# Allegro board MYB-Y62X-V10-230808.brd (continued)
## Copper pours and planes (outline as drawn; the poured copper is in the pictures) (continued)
GND on TOP: 170.1,77.6 169.72,77.6 168.45,76.33 163.75,76.33 162.23,77.85 162.23,81.53 161.72,82.04 160.07,82.04 159.94,81.92 159.94,80.39 159.56,80.01 156.38,80.01 155.62,80.77 153.84,80.77 151.68,82.93 135.56,82.93 134.79,82.17 134.79,79.88 135.68,78.99 138.22,78.99 141.91,75.31 151.56,75.31 151.94,75.69 159.99,75.69 160.63,75.06 161.24,75.06 163.24,73.05 163.24,71.12 162.1,69.98 160.83,69.98 160.75,69.9 160.75,69.32 160.85,69.22 161.59,69.22 161.9,68.91 161.9,67.92 161.54,67.56 151.05,67.56 148.26,64.77 148.26,61.47 148.89,60.83 153.72,60.83 157.4,64.52 171.88,64.52 172.13,64.77 172.13,80.14 171.88,80.39 169.72,80.39 169.46,80.64 169.08,80.64 168.96,80.52 168.96,79.25 169.85,78.36 169.85,77.85 169.72,77.72 170.1,77.72
GND on TOP: 168.96,84.07 171.75,84.07 172,83.82 172,82.3 171.75,82.04 168.96,82.04 168.7,82.3 168.7,83.82
GND on TOP: 144.95,56.01 144.95,55.5 146.48,53.98 149.4,53.98 149.53,53.85 149.53,52.32 149.78,52.07 152.83,52.07 153.21,52.45 153.21,54.99 153.46,55.24 154.99,55.24 155.24,54.99 155.24,52.58 154.43,51.77 154.43,49.73 154.28,49.58 153.39,49.58 153.39,50.75 152.7,51.44 149.27,51.44 149.02,51.69 149.02,53.21 148.76,53.47 146.48,53.47 145.84,54.1 145.21,54.1 144.95,53.85 144.95,53.47 144.83,53.34 144.06,53.34 143.94,53.47 143.94,56.01 144.06,56.13 144.83,56.13
GND on TOP: 147.62,90.68 147.37,90.93 147.37,94.39 148.38,95.4 148.38,96.9 148.51,97.03 149.78,97.03 149.91,96.9 149.91,92.74 150.57,92.08 154.22,92.08 154.35,91.95 154.35,90.93 154.1,90.68
GND on BOTTOM: 108,100.33 109.9,98.42 113.33,98.42 113.84,97.92 113.84,96.39 113.58,96.14 104.95,96.14 103.42,97.66 103.42,100.08 103.68,100.33
GND on BOTTOM: 30.11,124.49 104.06,124.49 104.06,108.71 103.17,107.82 99.74,107.82 99.23,108.33 99.23,111.76 97.96,113.03 92.63,113.03 89.07,116.59 33.96,116.59 32.11,114.74 30.91,114.74 30.11,115.54
GND on BOTTOM: 162.99,42.55 162.99,41.15 162.48,40.64 161.46,40.64 160.96,41.15 160.96,42.29 161.34,42.67 162.86,42.67
GND on BOTTOM: 18.72,83.06 18.72,81.28 18.84,81.15 20.11,81.15 20.37,81.41 20.37,83.06 20.11,83.31 18.97,83.31
GND on BOTTOM: 30.15,56.39 43.61,56.39 46.15,53.85 46.15,52.07 45.51,51.44 33.63,51.44 33.63,53.52 33.38,53.76 30.36,53.76 30.02,54.1 30.02,56.26
GND on BOTTOM: 88.44,34.9 92.1,34.9 92.22,34.77 92.22,32.92 91.41,32.11 88.41,32.11 88.21,32.31 88.21,34.67
GND on BOTTOM: 86.48,33.88 86.51,33.86 86.51,32.92 88.18,31.24 92.05,31.24 92.48,30.81 92.48,30.07 92.2,29.79 87.63,29.79 87.45,29.97 87.45,30.33 87.5,30.38 87.5,31.06 87.14,31.42 85.67,31.42 85.26,31.83 85.26,36.07 84.37,36.96 84.37,38.73 84.07,39.04 81.73,39.04 81.68,39.09 81.68,39.52 83.26,39.52 83.51,39.78 83.51,40.13 83.59,40.21 83.94,40.21 85.04,39.12 86.36,39.12 86.48,38.99
GND on BOTTOM: 111.76,34.87 115.41,34.87 115.57,34.72 115.57,32.89 114.96,32.28 111.68,32.28 111.48,32.49 111.48,34.59
GND on BOTTOM: 166.92,39.5 166.67,39.75 166.67,41.66 167.69,42.67 167.81,42.67 168.07,42.93 168.07,46.99 167.56,47.5 167.56,56.13 165.02,58.67 157.4,58.67 156.26,57.53 156.26,54.48 156,54.23 154.35,54.23 154.1,54.48 154.1,56.39 153.23,57.25 148.87,57.25 145.67,60.45 145.67,72.72 146.05,73.1 147.67,73.1 148.87,71.91 148.87,71.15 148.69,70.97 146.71,70.97 146.48,70.74 146.48,68.48 147.11,67.84 150.01,67.84 150.34,67.51 150.34,64.57 150.97,63.93 170.25,63.93 170.91,64.59 172.18,64.59 172.59,64.19 172.59,41.58 172.16,41.15 170.1,41.15 169.97,41.02 169.97,39.75 169.72,39.5
GND on BOTTOM: 72.06,39.47 71.47,40.06 71.47,44.86 73.61,46.99 73.61,47.98 73.88,48.26 77.59,48.26 78.94,46.91 86.61,46.91 87.02,46.51 87.02,42.9 85.82,41.71 83.21,41.71 82.6,41.1 80.26,41.1 78.63,39.47
GND on BOTTOM: outline of 93 points within 40.56,7.24 123.77,41.91
GND on BOTTOM: 132,33.48 125.09,33.48 124.81,33.2 124.81,28.02 125.29,27.53 127.33,27.53 127.71,27.15 127.71,25.91 127.96,25.65 128.37,25.65 128.85,26.14 130.35,26.14 130.73,25.76 131.54,25.76 132.05,26.26 133.14,26.26 133.4,26.52 134.57,26.52 134.69,26.64 134.69,31.22 134.57,31.34 133.42,31.34 132.1,32.66 132.1,33.38
GND on BOTTOM: 115.35,95.08 115.01,94.74 115.01,91.08 115.46,90.63 115.85,90.63 116.53,89.94 119.88,89.94 120.19,89.64 144.04,89.64 144.55,89.13 145.84,89.13 146.2,89.48 152.29,89.48 153.72,90.91 153.72,92.94 150.9,95.76 131.42,95.76 130.74,95.08
GND on BOTTOM: 14.78,6.22 14.52,6.48 14.52,11.05 15.16,11.68 16.43,11.68 17.45,12.7 17.45,14.35 16.18,15.62 14.52,15.62 12.87,13.97 8.56,13.97 7.92,14.61 7.92,86.06 8.3,86.44 12.92,86.44 13,86.36 13,62.74 14.91,60.83 25.57,60.83 26.21,60.2 26.21,57.78 25.07,56.64 25.07,52.07 24.68,51.69 18.97,51.69 18.72,51.94 18.72,52.81 19.35,53.44 19.35,55.5 18.97,55.88 14.02,55.88 13.13,54.99 13.13,34.16 13.64,33.66 19.15,33.66 20.29,34.8 25.83,34.8 33.45,27.18 36.11,27.18 36.29,27 36.29,25.83 35.99,25.53 35.48,25.53 32.18,22.23 32.18,17.02 29.64,17.02 29.13,16.51 29.13,12.95 28.49,12.32 20.37,12.32 18.84,10.79 18.84,7.37 17.7,6.22
GND on BOTTOM: 65.02,112.93 79.24,112.93 79.7,113.39 87.47,113.39 88.46,112.39 88.46,109.63 87.68,108.84 87.68,107.29 87.58,107.19 85.67,109.09 82.72,109.09 82.17,109.65 81.05,109.65 80.92,109.78 80.92,110.54 80.82,110.64 74.06,110.64 73.45,110.03 68.09,110.03 68.02,109.96 68.02,106.48 67.59,106.05 65.58,106.05 65.17,105.64 65.17,103.38 64.92,103.12 63.34,103.12 63.19,102.97 62.51,102.97 60.3,105.18 45.11,105.18 44.65,105.64 44.65,110.11 45.08,110.54 64.74,110.54 64.92,110.72 64.92,112.83
GND on BOTTOM: 158.43,8.52 159.18,9.27 170.73,9.27 170.86,9.4 170.86,13.46 172,14.61 172,35.69 171.12,36.58 165.15,36.58 164.38,35.81 164.38,21.34 163.11,20.07 160.57,20.07 156.51,16 151.3,16 151.24,16.07 150.22,16.07 149.78,15.62 149.78,13.46 148.23,11.91 148.23,8.56 148.92,7.87 158.37,7.87 158.43,7.94
GND on BOTTOM: 115.58,31.22 115.58,29.97 115.45,29.84 110.88,29.84 110.75,29.97 110.75,31.24 110.5,31.5 108.85,31.5 108.47,31.88 108.47,34.38 108.71,34.62 109.29,34.62 110.03,33.88 110.03,32.94 111.76,31.22
GND on BOTTOM: 56.93,47.51 56.93,49.16 58.97,51.21 58.97,60.2 55.93,63.25 55.93,72.26 56.31,72.64 61.34,72.64 63.92,70.07 63.92,50.95 62.66,49.7 62.66,49.66 62.53,49.53 62.53,47.37 62.4,47.24 57.2,47.24
GND on BOTTOM: 19.5,107.49 18.67,108.33 18.67,111.33 17.8,112.19 14.78,112.19 13.76,113.21 13.76,117.35 14.14,117.73 16.18,117.73 17.19,118.75 17.19,120.65 16.18,121.67 14.4,121.67 14.04,122.02 14.04,124.49 29.38,124.49 29.38,112.14 24.74,107.49
GND on BOTTOM: 142.82,16.51 142.82,14.88 143.02,14.68 145.59,14.68 146.38,13.89 146.38,13.11 146.6,12.88 148.26,12.88 148.76,13.39 148.76,13.92 148.56,14.12 147.27,14.12 146.63,14.76 146.63,16.79 146.35,17.07 143.18,17.07 142.97,17.27 142.97,17.68 143.18,17.88 143.84,17.88 143.89,17.93 143.89,18.47 143.66,18.69 140.64,18.69 140.1,19.23 136.78,19.23 136.39,18.85 136.39,11.35 136.62,11.13 137.79,11.13 137.94,11.28 137.94,16.71 138.96,17.73 141.6,17.73
GND on BOTTOM: 39.42,112.65 37.13,112.65 25.45,100.97 19.22,100.97 18.08,99.82 16.56,99.82 16.18,99.44 16.18,97.54 17.83,95.89 28.88,95.89 33.05,91.71 53.91,91.71 54.53,92.33 55.95,92.33 56.43,91.85 56.43,88.14 57.32,87.25 63.24,87.25 64,88.01 64,94.46 63.6,94.87 61.77,94.87 57.83,98.81 41.96,98.81 40.18,100.58 40.18,111.89
GND on BOTTOM: 38.48,82.98 38.1,82.6 38.1,79.3 37.66,78.87 36.22,78.87 35.86,79.22 35.86,80.37 35.66,80.57 29.21,80.57 28.16,79.53 28.16,74.22 28.9,73.48 45.41,73.48 46.43,74.5 46.43,82.14 49.75,85.47 56.03,85.47 56.28,85.72 56.28,86.11 53.89,88.49 49.73,88.49 49.4,88.82 30.02,88.82 29.92,88.72 29.92,87.93 31.62,86.23 31.62,84.99 31.97,84.63 38.32,84.63 38.48,84.48
GND on BOTTOM: 155.37,84.96 154.73,84.96 153.46,83.69 140.48,83.69 140.18,83.39 140.18,82.78 144.6,78.36 159.81,78.36 160.07,78.11 160.96,78.11 164.13,81.28 164.13,86.11 162.48,87.76 161.46,87.76 161.08,87.38 161.08,86.49 163.24,84.33 163.24,82.3 162.99,82.04 162.35,82.04 161.21,83.19 161.21,84.2 160.32,85.09 155.49,85.09
GND on BOTTOM: 137.08,79.45 135.07,79.45 134.72,79.1 134.72,78.71 134.51,78.51 131.95,78.51 131.06,77.62 131.06,75.06 136.01,70.1 136.01,69.32 142.41,62.92 142.41,54.74 143.48,53.67 144.88,53.67 147.47,51.08 150.8,51.08 151.02,51.31 151.02,52.37 151.01,52.39 151.01,52.74 144.27,59.49 144.27,72.26
GND on BOTTOM: 162.61,97.16 166.04,97.16 166.42,97.54 166.42,99.44 166.16,99.69 161.97,99.69 161.72,99.44 161.72,98.04
GND on BOTTOM: 124.13,32.16 122.45,32.16 122.12,31.83 122.12,30.76 121.81,30.45 120.98,30.45 120.54,30.02 120.54,24.31 120.93,23.93 126.59,23.93 126.72,24.05 126.72,26.34 126.39,26.67 124.66,26.67 124.3,27.03 124.3,31.98
GND on BOTTOM: 80.56,24.23 79.88,24.92 79.88,24.94 73.71,31.11 73.71,35.31 73.96,35.56 76.12,35.56 76.5,35.94 76.5,36.58 76.75,36.83 79.8,36.83 79.93,36.7 79.93,35.05 80.56,34.42 81.45,34.42 83.1,32.77 83.1,25.04 83.21,24.94 84.63,24.94 85.19,25.5 95.58,25.5 95.93,25.86 95.93,26.39 96.01,26.47 97.43,26.47 97.99,27.03 97.99,28.68 98.29,28.98 99.51,28.98 101.27,30.73 101.27,44.07 99.61,45.72 99.61,46.61 100.12,47.12 103.04,47.12 103.42,46.74 103.42,42.16 104.57,41.02 104.57,40.26 103.93,39.62 103.93,37.26 104.11,37.08 105.2,37.08 105.71,36.58 105.71,24.56 105.38,24.23
GND on BOTTOM: 162.96,22.91 162.25,23.62 157.12,23.62 156.74,24 156.74,31.7 155.8,32.64 153.72,32.64 153.21,32.13 153.21,28.32 153.46,28.07 154.86,28.07 154.99,27.94 154.99,26.42 154.73,26.16 153.84,26.16 153.46,26.54 146.35,26.54 145.21,27.69 145.21,32 145.46,32.26 146.48,32.26 147.62,33.4 147.62,34.67 159.94,34.67 161.82,32.79 161.82,30.76 162.02,30.56 162.35,30.56 162.63,30.84 163.34,30.84 163.52,30.66 163.52,23.14 163.29,22.91
GND on BOTTOM: 52.65,61.39 54.61,61.39 56.94,59.05 56.94,53.16 51.33,47.55 49.93,47.55 49.35,48.13 49.35,53.14 48.31,54.18 48.31,58.98 48.99,59.66 50.92,59.66
GND on BOTTOM: 29.78,39.51 30.78,40.51 42.67,40.51 43.28,39.9 43.28,34.04 42.34,33.1 35.94,33.1 34.91,32.07 31.15,32.07 29.78,33.44
GND on ART03: 19.53,107.49 18.69,108.33 18.69,111.28 17.78,112.19 14.8,112.19 14.04,112.95 14.04,124.49 29.36,124.49 29.36,109.98 26.87,107.49
GND on ART03: 166.92,40.26 168.83,40.26 169.21,39.88 169.21,24.38 164.13,19.3 160.96,19.3 160.96,21.59 164,24.64 164,37.34
GND on ART03: 72.82,35.05 72.82,33.02 73.33,32.51 82.85,32.51 85.39,29.97 87.04,29.97 87.42,30.35 87.42,30.61 85.64,32.38 84.5,32.38 82.85,34.04 81.2,34.04 81.07,33.91 78.79,33.91 77.52,35.18 72.94,35.18
GND on ART03: 68.09,124.49 103.93,124.49 103.93,108.76 102.56,107.39 100.02,107.39 98.4,109.02 98.4,116.28 98.42,116.31 98.01,116.71 97.2,116.71 96.19,115.7 67.92,115.7 67.76,115.85 67.76,124.16
GND on ART03: 33.61,99.31 42.21,99.31 42.87,98.65 42.87,83.85 42.13,83.11 30.7,83.11 30.37,83.44 28.93,83.44 28.62,83.13 28.62,81.46 28.47,81.31 26.54,81.31 26.25,81.6 26.25,91.95
GND on ART03: 77.64,7.24 76.5,8.38 76.5,19.05 75.99,19.56 73.2,19.56 72.94,19.3 72.94,14.73 73.33,14.35 73.33,13.21 73.07,12.95 72.06,12.95 71.8,12.7 71.8,10.41 71.42,10.03 68.88,10.03 67.74,8.89 62.28,8.89 61.64,9.53 61.64,18.92 61.9,19.18 63.55,19.18 64.69,20.32 64.69,23.75 64.94,24 67.23,24 69.8,21.44 69.82,21.46 76.63,21.46 77.39,22.23 119.81,22.23 123.36,18.67 123.36,17.91 123.11,17.65 120.44,17.65 117.39,20.7 106.22,20.7 105.33,19.81 105.33,16.26 105.08,16 98.22,16 97.58,16.64 97.58,18.8 95.8,20.57 83.36,20.57 82.72,19.94 82.72,16.26 82.47,16 80.95,16 79.93,14.99 79.93,9.53 80.44,9.02 80.44,7.37 80.31,7.24
GND on ART03: 139.24,70.1 140.64,68.71 150.44,68.71 151,69.27 151.61,69.27 151.84,69.49 151.84,70.26 154.22,72.64 154.22,76.38 153.77,76.83 140.03,76.83 139.24,76.05
GND on ART03: 157.53,53.19 157.53,52.45 156.89,51.82 156.89,50.8 156.38,50.29 154.22,50.29 153.93,50 153.95,49.99 153.95,49.73 154.05,49.63 157.48,49.63 161.26,45.85 162.78,45.85 163.06,46.13 163.06,48.26 163.24,48.44 163.88,48.44 164,48.31 164.23,48.31 164.38,48.46 164.38,49.53 164.26,49.66 163.42,49.66 162.98,50.1 162.98,51.02 159.36,54.64 157.73,54.64 157.54,54.44 157.54,53.2
GND on ART03: 114.73,94.87 130.6,94.87 131.75,96.01 156.51,96.01 159.3,93.22 170.48,93.22 171.88,91.82 171.88,72.06 171.22,71.4 168.65,71.4 162.07,77.98 157.65,77.98 157.63,78 130.09,78 129.43,78.66 129.43,87.3 131.34,89.2 131.34,90.42 131.47,90.55 129.59,90.55 128.06,92.08 126.67,92.08 126.41,92.33 119.81,92.33 118.79,91.31 115.62,91.31 114.73,92.2
GND on ART03: 23.67,90.7 22.58,90.7 22.32,90.45 22.32,88.29 18.82,84.79 18.82,80.62 19.02,80.42 22.96,80.42 23.8,81.25 23.8,90.58
GND on ART03: 28.88,81.03 28.88,78.56 29.08,78.36 40.03,78.36 40.18,78.51 40.18,81.66 40.05,81.79 37,81.79 36.5,81.28 29.13,81.28
GND on ART03: 50.34,42.8 50.34,35.46 51.2,34.59 52.7,34.59 53.01,34.29 55.95,34.29 56.68,35.01 60.97,35.01 62.53,36.58 62.53,41.53 61.26,42.8
GND on ART03: 112.44,44.45 120.82,44.45 126.03,49.66 126.03,49.68 131.43,55.08 131.43,55.89 131.31,56.01 130.76,56.01 129.33,54.58 116.12,54.58 115.57,54.03 115.57,52.45 114.7,51.59 111.63,51.59 110.28,50.24 110.28,46.61
GND on ART03: 153.46,25.53 152.19,26.8 147.37,26.8 145.72,28.45 145.72,41.05 147.09,42.42 162.73,42.42 162.99,42.16 162.99,40.51 162.73,40.26 160.19,40.26 159.91,40.54 155.09,40.54 154.86,40.31 154.86,37.95 154.43,37.52 151.35,37.52 151.05,37.21 151.05,35.64 151.38,35.31 154.91,35.31 155.49,34.72 155.49,26.16 154.86,25.53
GND on ART03: 10.59,89.36 11.98,90.75 11.98,102.36 13.51,103.89 15.16,103.89 18.21,106.93 18.21,111 17.45,111.76 14.27,111.76 13.51,112.52 13.51,114.55 13.38,114.68 8.05,114.68 7.79,114.43 7.79,89.66 8.1,89.36
GND on ART03: 60.75,95.89 63.29,95.89 64.05,95.12 64.05,89.15 63.8,88.9 63.8,86.49 62.91,85.6 62.91,83.69 63.17,83.44 64.44,83.44 64.82,83.06 64.82,51.38 64.33,50.9 61.18,50.9 60.7,51.38 60.7,52.6 61.11,53.01 62.23,53.01 62.73,53.52 62.73,66.65 61.34,68.05 58.49,68.05 57.7,68.83 57.7,88.52 57.2,89.03 57.2,92.33
GND on ART03: 85.26,34.16 85.26,33.66 88.06,30.86 95.68,30.86 97.71,32.89 109.52,32.89 109.77,33.15 109.77,34.42 109.52,34.67 98.85,34.67 98.6,34.92 96.06,34.92 95.55,34.42 85.52,34.42
GND on ART03: 65.58,36.07 73.2,36.07 75.48,38.35 80.56,38.35 82.22,36.7 89.45,36.7 89.96,36.2 95.42,36.2 96.19,36.96 96.19,37.85 95.55,38.48 82.6,38.48 81.2,39.88 75.99,39.88 75.23,40.64 66.7,40.64 66.62,40.72 66.62,41.1 67.13,41.61 71.62,41.61 71.93,41.91 71.93,43 72.39,43.46 72.39,44.25 72.01,44.63 65.1,44.63 64.36,43.89 64.36,37.29
GND on ART03: 40.56,108.69 39.59,109.65 34.49,109.65 29.69,104.85 20.44,104.85 19.86,104.27 19.86,95 20.62,94.23 24.56,94.23 32.3,101.98 40.05,101.98 40.56,102.49
GND on ART03: 122.47,30.86 133.02,30.86 134.79,29.08 139.75,29.08 140.25,28.57 140.25,21.97 139.11,20.83 132.25,20.83 130.98,22.1 130.98,23.75 125.9,23.75 125.78,23.62 125.78,23.88 126.03,24.13 126.03,26.29 122.47,29.84
GND on ART03: outline of 156 points within 12.62,5.21 58.85,69.85
GND on ART03: 28.47,72.14 41.3,72.14 45.11,68.33 46.17,68.33 46.55,67.94 46.55,63.45 46.22,63.12 43.02,63.12 42.59,62.69 42.59,61.77 42.44,61.62 40.76,61.62 40.43,61.95 40.43,67.39 38.99,68.83 31.8,68.83 29.87,70.76 28.49,70.76 28.37,70.89 28.37,72.03
GND on ART03: 142.54,21.08 142.54,13.84 143.68,12.7 145.72,12.7 145.84,12.83 146.48,12.83 148.13,11.18 148.13,8.64 148.89,7.87 158.37,7.87 158.42,7.92 158.42,8.51 159.18,9.27 170.86,9.27 170.86,13.08 172.51,14.73 172.51,38.99 172.26,39.24 170.73,39.24 170.48,38.99 170.48,22.73 166.04,18.29 160.7,18.29 160.7,13.72 160.19,13.21 159.56,13.21 157.65,15.11 152.7,15.11 152.07,14.48 152.07,13.08 151.56,12.57 150.67,12.57 150.03,13.21 150.03,14.1 149.78,14.35 148.38,14.35 144.95,17.78 144.95,20.7 144.32,21.34 142.79,21.34
GND on ART03: 66.82,124.49 66.98,124.33 66.98,116.03 66.65,115.7 63.65,115.7 60.35,112.39 31.87,112.39 30.83,113.44 30.83,123.72 31.6,124.49
GND on POW04: outline of 106 points within 5.51,0.51 174.49,124.49
GND on GND05: outline of 97 points within 5.51,0.51 174.49,124.49
GND_EARTH on TOP (solid shape): outline of 212 points within 5.95,118.33 11.66,124.04
GND_EARTH on TOP (solid shape): outline of 212 points within 5.95,0.95 11.66,6.67
GND_EARTH on TOP (solid shape): outline of 212 points within 168.34,118.33 174.05,124.04
GND_EARTH on TOP (solid shape): outline of 212 points within 168.34,0.95 174.05,6.67
GND_EARTH on BOTTOM (solid shape): outline of 212 points within 5.95,118.33 11.66,124.04
GND_EARTH on BOTTOM (solid shape): outline of 212 points within 5.95,0.95 11.66,6.67
GND_EARTH on BOTTOM (solid shape): outline of 212 points within 168.34,118.33 174.05,124.04
GND_EARTH on BOTTOM (solid shape): outline of 212 points within 168.34,0.95 174.05,6.67
GND_EARTH on TOP: outline of 110 points within 5.51,0.51 174.49,124.49
GND_EARTH on BOTTOM: outline of 110 points within 5.51,0.51 174.49,124.49
GND_EARTH on GND02: outline of 110 points within 5.51,0.51 174.49,124.49
GND_EARTH on ART03: outline of 110 points within 5.51,0.51 174.49,124.49
GND_EARTH on POW04: outline of 110 points within 5.51,0.51 174.49,124.49
GND_EARTH on GND05: outline of 110 points within 5.51,0.51 174.49,124.49
VDD_1V2 on TOP: 150.8,21.34 153.08,21.34 153.21,21.21 153.21,20.32 152.95,20.07 150.92,20.07 150.8,20.19
VDD_1V2 on TOP: 149.78,54.99 149.78,54.48 150.03,54.23 152.45,54.23 152.57,54.36 152.57,56.26 152.45,56.39 151.68,56.39 151.56,56.26 151.56,55.37 151.3,55.12 149.91,55.12
VDD_1V2 on TOP: 154.91,49.73 154.91,47.32 156.82,45.42 156.82,44.78 157.53,44.07 157.53,43.94 157.51,43.93 157.51,43.03 159.18,41.36 159.18,40.31 159.86,39.62 160.22,39.62 160.5,39.34 160.5,37.67 160.78,37.39 162.15,37.39 162.28,37.52 162.28,40.23 161.57,40.94 161.26,40.94 160.69,41.52 160.69,42.33 160.24,42.77 159.69,42.77 159.08,43.38 159.08,44.73 158.43,45.38 158.43,46.62 156.59,48.46 156.59,49.73 156.38,49.94 155.11,49.94
VDD_1V2 on BOTTOM: 151.51,56.54 151.51,54.33 152.85,52.98 152.85,51.54 153.77,50.62 153.77,50.52 153.92,50.37 154.28,50.37 154.54,50.1 154.54,49.03 155.16,48.41 156,48.41 156.16,48.56 156.16,50.11 155.27,51 155.27,53.34 154.87,53.73 153.96,53.73 153.59,54.1 153.59,54.71 153.06,55.24 153.06,56.44 152.8,56.69 151.66,56.69
VDD_1V2 on ART03: 150.82,22.23 150.82,19.74 151.05,19.51 153.08,19.51 153.36,19.79 153.36,20.6 153.62,20.85 159.13,20.85 163.47,25.2 163.47,38.43 163.22,38.68 160.19,38.68 159.48,37.97 159.48,25.07 156.89,22.48 151.08,22.48
VDD_1V8 on TOP: 11.32,103.58 12.37,103.58 12.59,103.35 12.59,102.39 12.29,102.08 11.38,102.08 11.2,102.26 11.2,103.45
VDD_1V8 on BOTTOM: 151.63,77.98 156.36,77.98 157.81,76.53 163.6,76.53 166.44,79.38 166.44,88.65 163.17,91.92 155.19,91.92 151.23,95.89 115.36,95.89 114.98,96.27 114.98,98.37 115.11,98.5 160.7,98.5 162.99,96.22 170.91,96.22 172.39,94.74 172.39,67.01 169.85,64.47 151.23,64.47 150.8,64.9 150.8,77.14
VDD_1V8 on BOTTOM: 11.83,101.75 25.42,101.75 36.8,113.13 78.86,113.13 79.45,113.72 87.65,113.72 89.25,112.12 89.25,110.64 89.58,110.31 91.79,110.31 92.38,110.9 92.38,111.79 92.05,112.12 91.33,112.12 91,112.45 91,113.59 88.52,116.08 34.92,116.08 23.87,105.03 11.98,105.03 11.22,104.27 11.22,102.36
VDD_1V8 on POW04: 82.42,101.7 82.42,100.3 83.51,99.21 91.87,99.21 92.71,98.37 92.71,93.14 94.28,91.57 111.5,91.57 112.82,92.89 113.86,92.89 115.88,94.91 118.07,94.91 118.54,95.38 118.54,97.54 118.28,97.79 117.29,97.79 117.27,97.76 113.74,97.76 113.43,97.46 113.43,96.22 113.23,96.01 104.44,96.01 103.42,97.03 103.42,98.42 103.3,98.55 102.03,98.55 98.07,102.51 83.23,102.51
VDD_3V3 on TOP: 64.18,95.63 64.18,93.73 64.31,93.6 65.2,93.6 65.32,93.73 65.32,95.63 65.2,95.76 64.31,95.76
VDD_3V3 on TOP: 37.51,27.69 37.77,27.94 37.77,29.08 37.46,29.39 33.73,29.39 33.52,29.18 33.52,28.35 34.18,27.69
VDD_3V3 on TOP: 122.09,59.31 122.09,57.15 122.22,57.02 123.11,57.02 123.24,57.15 123.24,59.31 123.11,59.44 122.22,59.44
VDD_3V3 on TOP: 82.04,34.82 81.96,34.75 80.9,34.75 80.74,34.9 80.74,35.74 80.87,35.86 81.91,35.86 82.04,35.74
VDD_3V3 on TOP: 149.27,21.21 149.27,20.19 149.4,20.07 150.29,20.07 150.41,20.19 150.41,21.21 150.29,21.34 149.4,21.34
VDD_3V3 on TOP: 163.88,86.49 167.94,86.49 168.19,86.23 168.19,85.98 167.94,85.72 164.89,85.72 164.64,85.47 164.64,84.71 164.51,84.58 163.37,84.58 163.24,84.71 163.24,85.47 163.5,85.72 163.75,85.72 163.88,85.85
VDD_3V3 on TOP: 115.49,96.77 115.49,91.95 115.74,91.69 115.74,91.19 115.49,90.93 113.84,90.93 113.71,91.06 113.71,92.58 114.35,93.22 114.35,96.77 114.47,96.9 115.36,96.9
VDD_3V3 on TOP: 140.76,96.9 140.76,93.85 140.38,93.47 139.24,93.47 139.11,93.34 139.11,92.46 139.24,92.33 142.79,92.33 142.92,92.46 142.92,92.84 142.03,93.73 142.03,96.9 141.91,97.03 140.89,97.03
VDD_3V3 on TOP: 80.69,104.39 81.3,104.39 81.71,103.99 81.71,102.9 81.33,102.51 80.72,102.51 80.56,102.67 80.56,104.27
VDD_3V3 on TOP: 145.59,55.5 146.73,54.36 148.64,54.36 148.76,54.48 148.76,54.86 148.64,54.99 146.99,54.99 146.73,55.24 146.73,56.52 146.6,56.64 145.72,56.64 145.59,56.52
VDD_3V3 on TOP: 152.19,97.03 152.19,93.98 151.81,93.6 150.67,93.6 150.54,93.47 150.54,92.58 150.67,92.46 154.22,92.46 154.35,92.58 154.35,92.96 153.46,93.85 153.46,97.03 153.34,97.16 152.32,97.16
VDD_3V3 on TOP: 101.36,39.12 103.39,39.12 103.51,39.24 103.51,40.26 103.39,40.39 101.36,40.39 101.23,40.26 101.23,39.24
VDD_3V3 on TOP: 128.19,96.77 128.19,91.19 128.06,91.06 126.41,91.06 126.16,91.31 126.16,92.71 126.92,93.47 126.92,96.52 127.17,96.77
VDD_3V3 on TOP: 169.08,43.81 169.08,42.93 170.23,41.78 170.23,39.75 170.48,39.5 171.5,39.5 171.88,39.88 171.88,43.69 171.75,43.81
VDD_3V3 on BOTTOM: 92.88,116.81 92.88,115.52 93.21,115.19 101.85,115.19 102.18,115.52 102.18,116.59 101.75,117.02 93.09,117.02
VDD_3V3 on BOTTOM: 33.32,30.66 33.32,28.83 33.57,28.57 36.52,28.57 38.1,30.15 43.56,30.15 44.52,29.18 44.52,27.64 44.57,27.58 46.02,27.58 46.14,27.7 46.14,32.37 45.89,32.61 37.44,32.61 37.44,32.59 35.71,30.86 33.52,30.86
VDD_3V3 on BOTTOM: 170.43,40.72 170.43,39.67 169.95,39.19 162.02,39.19 161.74,38.91 161.74,37.49 161.92,37.31 170.53,37.31 171.83,38.61 171.83,40.59 171.7,40.72
VDD_3V3 on POW04: 15.29,96.55 21.81,96.55 25.6,100.33 62.23,100.33 67.13,95.43 69.13,95.43 70.43,96.72 74.57,96.72 74.88,97.03 74.88,102.13 77.31,104.57 81.56,104.57 83.03,103.1 83.03,100.94 84.35,99.62 92.2,99.62 98.45,93.37 113.99,93.37 115.69,95.07 166.39,95.07 166.92,94.54 166.92,85.01 164.94,83.03 164.94,39.7 165.17,39.47 165.17,21.44 162.3,18.57 150.64,18.57 145.44,23.77 122.93,23.77 122.14,22.99 83.49,22.99 76.73,16.23 59.15,16.23 57.53,14.61 53.87,14.61 52.87,15.61 51.53,15.61 51.53,16.51 51.08,16.97 49.88,16.97 49.88,17.7 49.22,18.36 49.22,20.35 47.98,21.59 46.78,21.59 46.71,21.67 46.71,22.1 46.78,22.17 49.88,22.17 50.42,22.71 50.42,24.41 46.27,28.55 45.54,28.55 45.34,28.75 45.34,29.64 45.18,29.79 43.89,29.79 43.76,29.92 43.76,34.98 46.48,37.69 46.48,37.72 47.27,38.51 47.27,42.7 46.66,43.31 34.9,43.31 30.25,38.66 18.33,38.66 14.68,42.32 14.68,67.31 16.02,68.66 16.02,87.58 14.47,89.13 14.47,95.73
VDD_3V9 on TOP: 46.5,52.78 47.84,54.11 47.84,56.35 47.01,57.18 35.86,57.18 35.86,57.15 33.07,57.15 32.43,57.78 27.35,57.78 27.03,58.1 27.03,60.01 27.22,60.2 47.04,60.2 49.45,57.78 49.45,52.2 49.06,51.8 49.06,48.9 48.93,48.77 48.92,48.77 48.71,48.56 46.78,48.56 46.5,48.84
VDD_3V9 on TOP: 31.54,65.66 31.67,65.53 35.1,65.53 35.48,65.91 35.48,69.04 35.63,69.19 36.34,69.19 36.88,69.72 36.88,71.3 36.39,71.78 34.84,71.78 34.08,72.54 31.67,72.54 31.54,72.42
VDD_3V9 on BOTTOM: 27.35,57.15 28.24,57.15 28.37,57.28 28.37,59.94 28.11,60.2 27.35,60.2 27.1,59.94 27.1,57.4
VDD_3V9 on BOTTOM: 44.62,57.28 44.62,59.05 44.5,59.18 44.5,59.59 44.62,59.72 46.83,59.72 47.06,59.49 47.06,57.53 46.81,57.28 45.59,57.28 45.59,58.78 45.41,58.78 45.41,57.28 45.11,57.28 45.11,58.78 44.9,58.78 44.9,57.28
VDD_3V9 on ART03: 30.65,67.77 38.32,67.77 39.26,66.83 39.26,61.65 40.51,60.4 47.24,60.4 47.52,60.12 47.52,57.68 47.32,57.48 37.03,57.48 35.84,58.67 35.84,65.28 35.66,65.46 35,65.46 34.97,65.43 32.53,65.43 32.23,65.13 32.23,58.93 31.54,58.24 27.33,58.24 27.02,58.55 27.02,60.07 27.21,60.26 29.37,60.26 30.1,60.99 30.1,67.21
VDD_5V on TOP: 55.67,27.05 55.67,24.26 55.8,24.13 58.85,24.13 58.97,24.26 58.97,25.15 58.85,25.27 57.07,25.27 56.82,25.53 56.82,27.05 56.69,27.18 55.8,27.18
VDD_5V on TOP: 109.29,100.58 109.29,99.34 109.57,99.06 112.75,99.06 112.87,99.19 112.87,100.58 112.72,100.74 109.44,100.74
VDD_5V on TOP: 39.04,65.28 40.31,65.28 42.59,67.56 42.59,68.2 42.85,68.45 47.8,68.45 47.93,68.33 47.93,66.8 47.8,66.67 43.1,66.67 41.96,65.53 41.07,65.53 40.43,64.9 39.16,64.9 39.04,65.02
VDD_5V on TOP: 130.22,22.99 130.22,21.59 130.48,21.34 131.62,21.34 131.87,21.59 131.87,22.99 131.75,23.11 130.35,23.11
VDD_5V on TOP: 76.15,97.18 75.23,97.18 73.35,99.06 70.79,99.06 70.51,98.78 70.51,97.13 70.63,97 73.71,97 73.83,96.88 74.55,96.88 74.57,96.85 76.17,96.85 76.22,96.9 76.22,97.1
VDD_5V on TOP: 163.95,43.69 167.05,43.69 167.05,42.93 166.67,42.55 166.42,42.55 165.91,42.04 165.91,40.89 165.65,40.64 164.13,40.64 163.88,40.89 163.88,43.61
VDD_5V on TOP: 33.57,39.34 33.57,42.29 34.29,43 35.48,43 36.93,44.45 46.55,44.45 48.26,42.75 48.26,41.58 50.21,39.62 51.42,39.62 51.44,39.6 51.44,39.38 51.38,39.32 50.03,39.32 49.83,39.12 46.15,39.12 45.89,39.37 45.89,40.77 45.64,41.02 45.51,41.02 45.5,41.01 44.61,41.01 44.57,41.05 34.95,41.05 34.58,40.68 34.58,39.38 34.26,39.07 33.85,39.07
VDD_5V on TOP: 124.28,24.46 124.28,23.06 124.53,22.81 125.68,22.81 125.93,23.06 125.93,24.46 125.8,24.59 124.41,24.59
VDD_5V on TOP: 167.43,99.82 167.43,98.68 167.81,98.3 171.75,98.3 172,98.55 172,99.82 171.75,100.08 167.69,100.08
VDD_5V on TOP: 20.37,85.22 20.37,84.07 20.49,83.95 21.38,83.95 21.51,84.07 21.51,85.22 21.38,85.34 20.49,85.34
VDD_5V on BOTTOM: 32.36,70.59 45.94,70.59 47.94,68.59 47.93,68.58 47.93,66.83 47.77,66.67 37.77,66.67 34.16,63.07 34.16,61.87 33.73,61.44 23.06,61.44 22.63,61.87 22.63,64.77 22.88,65.02 24.48,65.02 26.81,67.35 26.81,67.98 27.35,68.53 30.3,68.53
VDD_5V on BOTTOM: 56.61,25.91 56.94,26.24 56.94,28.63 56.74,28.83 52.52,28.83 51.69,29.67 51.69,33.88 50.12,35.45 50.12,40.7 49.78,41.05 48.76,41.05 48.52,41.29 48.52,42.94 48.38,43.08 43.84,43.08 43.68,42.93 43.68,42.04 44.17,41.55 44.17,40.41 44.29,40.28 45.36,40.28 45.69,39.95 45.69,38.86 45.21,38.38 44.4,38.38 44.22,38.2 44.22,33.35 44.45,33.12 46.12,33.12 46.53,32.72 46.53,26.87 47.49,25.91
VDD_5V on BOTTOM: 163.37,42.55 163.37,40.77 163.5,40.64 165.91,40.64 166.04,40.77 166.04,41.78 165.91,41.91 165.02,41.91 164.89,42.04 164.89,42.29 165.27,42.67 167.05,42.67 167.31,42.93 167.31,43.69 167.18,43.81 165.15,43.81 163.88,42.55
VDD_5V on ART03: 109.39,99.31 110.87,99.31 113.53,96.65 157.22,96.65 159.71,94.16 170.63,94.16 172.31,95.83 172.31,99.67 171.95,100.03 162.58,100.03 161.57,99.01 114.02,99.01 112.29,100.74 109.39,100.74 109.2,100.55 109.2,99.5
VDD_5V on ART03: 54.78,26.01 55.11,25.68 57.5,25.68 59.28,27.46 65.78,27.46 67.53,25.7 97.2,25.7 97.61,25.3 103.68,25.3 104.29,25.91 118.77,25.91 118.84,25.83 120.93,25.83 122.81,23.95 122.81,22.45 123.72,21.54 126.11,21.54 126.82,20.83 131.77,20.83 132.23,21.29 132.23,23.19 131.49,23.93 126.18,23.93 125.62,24.49 124.99,24.49 124.1,25.37 124.1,26.39 120.39,30.1 117.65,30.1 116.28,28.73 110.56,28.73 110.28,28.45 110.11,28.45 108.96,29.59 98.85,29.59 98.22,28.96 93.24,28.96 92.43,28.14 86.97,28.14 85.24,29.87 85.19,29.87 82.93,32.13 69.24,32.13 66.98,34.39 56.82,34.39 54.78,32.36
VDD_5V on POW04: 75.28,96.67 75.28,97.43 74.85,97.87 74.85,101.42 77.36,103.94 81.81,103.94 82.93,102.82 98.04,102.82 101.84,99.02 111.34,99.02 111.78,99.47 112.09,99.47 112.19,99.57 112.19,100.58 112.06,100.71 111.88,100.71 111.88,100.74 103.02,100.74 95.27,108.48 74.82,108.48 73.55,107.21 73.55,104.14 72.31,102.9 72.31,102.87 72.06,102.62 70.91,102.62 70.53,102.23 70.53,96.39 70.66,96.27 74.88,96.27
VDD_5V on POW04: 47.93,43 48.26,42.67 48.26,39.9 43.99,35.64 43.99,32.41 43.53,31.95 37.11,31.95 34.72,29.57 31.54,29.57 29.31,31.8 18.74,31.8 11.17,39.37 11.17,63.75 15.95,68.53 24.94,68.53 25.45,68.02 25.45,61.32 24.81,60.68 21.28,60.68 20.14,59.54 20.14,45.11 23.69,41.55 33.52,41.55 34.97,43
VDD_5V on POW04: 124.57,20.28 125.22,19.63 128.62,19.63 129.46,18.8 141.55,18.8 143.2,17.14 145.59,17.14 146.48,16.26 146.48,15.7 147.11,15.06 155.6,15.06 155.61,15.05 162.39,15.05 169.62,22.28 169.62,91.24 172.39,94.01 172.39,99.77 172.08,100.08 166.98,100.08 166.19,99.29 166.19,85.32 164.56,83.69 164.56,43.79 163.75,42.98 163.75,21.77 160.98,19 149.78,19 145.36,23.42 124.63,23.42 124.57,23.36
VDD_5V_SW on TOP: 33.6,34.34 33.6,33.6 33.54,33.54 32.14,33.54 31.9,33.78 31.9,34.01 32,34.11 33.12,34.11 33.42,34.42 33.52,34.42
VDD_5V_SW on TOP: 32.56,37.9 32.56,37.24 32.64,37.16 33.24,37.16 33.37,37.03 33.37,36.55 33.45,36.47 33.96,36.47 34.06,36.58 34.06,38.1 33.27,38.89 31.95,38.89 31.57,39.27 31.57,42.27 31.26,42.57 30.83,42.57 30.55,42.29 30.55,38.53 30.98,38.1 32.36,38.1
VDD_5V_SW on BOTTOM: 33.96,38.1 33.96,37.47 33.45,36.96 33.45,33.91 33.19,33.66 31.92,33.66 31.67,33.91 31.67,37.34 32.69,38.35 33.7,38.35
VDD_12V on TOP: 30.58,37.49 32.3,35.76 33.14,35.76 33.22,35.69 33.22,34.7 33.12,34.59 32.1,34.59 31.78,34.91 31.78,35.29 31.43,35.65 30.69,35.65 30.53,35.81 30.27,35.81 30.26,35.8 25.09,35.8 25.08,35.81 20.34,35.81 20.19,35.97 20.19,37.34 20.34,37.49
VDD_12V on TOP: 7.79,24 12.11,24 13,23.11 13,19.81 12.62,19.43 8.68,19.43 7.79,20.32
VDD_12V on TOP: 35.89,82.22 36.67,81.43 37.51,81.43 37.54,81.41 37.54,80.42 37.38,80.26 36.85,80.26 35.75,81.37 34.93,81.37 34.82,81.48 29.16,81.48 29,81.64 29,84.48 29.27,84.75 33.82,84.75 35.89,82.68
VDD_12V on TOP: 15.92,101.09 15.92,100.33 16.18,100.08 17.83,100.08 18.08,100.33 18.08,100.97 17.83,101.22 16.05,101.22
VDD_12V on TOP: 21.89,85.34 21.89,84.07 22.02,83.95 22.91,83.95 23.03,84.07 23.03,85.22 22.91,85.34
VDD_12V on BOTTOM: 15.67,88.6 17.37,90.3 20.62,90.3 21.73,89.19 21.73,82.36 22.09,81.99 28.42,81.99 28.93,81.48 30.65,81.48 31.24,82.07 31.24,86.23 29.41,88.06 29.41,90.65 27.1,92.96 14.5,92.96 12.12,90.59 12.14,90.58 12.14,88.72 12.26,88.6
VDD_12V on ART03: 26.74,37.44 27.06,37.12 27.06,30.39 16.1,19.43 9.06,19.43 8.56,19.94 8.56,86.72 12.77,90.93 12.77,102.34 13.15,102.72 17.52,102.72 18.28,101.96 18.28,89.99 11.6,83.31 11.6,63.02 14.47,60.15 14.47,35.46 16.1,33.83 18.61,33.83 18.84,34.06 18.84,37.11 19.17,37.44
VDD_12VSW on TOP: 25.85,29.29 25.4,28.83 20.75,28.83 20.11,28.19 20.11,19.81 14.52,14.22 8.68,14.22 8.17,14.73 8.17,17.4 8.81,18.03 13.51,18.03 16.87,21.4 16.87,31.81 17.19,32.13 25.45,32.13 25.85,31.72
VDD_485_5V on TOP: 109.52,104.01 109.27,104.27 109.27,105.92 109.77,106.43 113.33,106.43 114.09,107.19 114.09,108.71 114.22,108.84 116.25,108.84 116.38,108.71 116.38,108.2 115.49,107.31 115.49,104.39 115.24,104.14 113.71,104.14 113.58,104.01
VDD_485_5V on TOP: 126.92,108.84 128.95,108.84 129.08,108.71 129.08,108.2 128.19,107.31 128.19,104.39 127.94,104.14 126.92,104.14 126.79,104.27 126.79,108.71
VDD_485_5V on ART03: 108.38,111.89 108.38,104.39 108.76,104.01 133.27,104.01 134.03,104.78 134.03,112.78 133.02,113.79 110.28,113.79
VDD_AUDIO_3V3 on TOP: 36.95,27.05 39.16,27.05 39.42,27.3 40.05,27.3 40.18,27.18 40.18,25.78 39.8,25.4 38.53,25.4 38.02,25.91 37.13,25.91 36.88,26.16 36.88,26.97
VDD_AUDIO_3V3 on ART03: 38.22,26.85 40.05,26.85 40.05,26.82 40.18,26.7 40.18,24.21 40.19,24.19 40.19,23.48 41.68,22 41.68,21.31 41.42,21.06 38.45,21.06 38.15,21.36 38.15,26.77
VDD_BAT on TOP: 116.76,58.27 116.96,58.06 120.75,58.06 121.08,58.39 121.08,59.21 119.91,60.38 116.86,60.38 116.76,60.27
VDD_BLE_3V3 on TOP: 58.21,96.14 64.69,96.14 65.07,96.52 65.07,97.54 64.56,98.04 60.5,98.04 59.86,98.68 59.86,98.7 59.74,98.83 59.74,100.23 59.64,100.33 59.36,100.33 59.28,100.25 59.28,98.86 59.13,98.7 58.14,98.7 58.01,98.83 58.01,100.23 57.91,100.33 57.6,100.33 57.53,100.25 57.53,96.82
VDD_CAN_5V on TOP: 152.32,104.14 152.83,104.14 153.21,104.52 153.21,105.41 153.59,105.79 153.97,105.79 154.1,105.92 154.1,106.93 153.97,107.06 152.32,107.06 152.07,106.81 152.07,104.39
VDD_CAN_5V on TOP: 140.89,104.01 141.4,104.01 141.78,104.39 141.78,105.28 142.16,105.66 142.54,105.66 142.67,105.79 142.67,106.81 142.54,106.93 140.89,106.93 140.64,106.68 140.64,104.27
VDD_CAN_5V on TOP: 167.43,103.89 167.94,103.38 171.75,103.38 171.88,103.5 171.88,105.16 171.5,105.54 167.69,105.54 167.43,105.28
VDD_CAN_5V on BOTTOM: 140.76,105.03 142.79,105.03 142.92,105.16 142.92,106.81 142.79,106.93 140.89,106.93 140.64,106.68 140.64,105.16
VDD_CAN_5V on BOTTOM: 152.19,105.16 154.22,105.16 154.35,105.28 154.35,106.93 154.22,107.06 152.32,107.06 152.07,106.81 152.07,105.28
VDD_CAN_5V on ART03: 140.38,113.16 140.38,104.9 141.78,103.5 151.56,103.5 152.07,104.01 159.43,104.01 159.94,103.5 171.5,103.5 171.75,103.76 171.75,105.79 171.24,106.3 169.08,106.3 161.34,114.05 141.27,114.05
VDD_IN on TOP: 26.49,13.08 27.99,11.58 27.99,8.84 28.29,8.53 29.84,8.53 30.15,8.84 30.15,13.46 28.49,15.11 26.69,15.11 26.49,14.91
VDD_IN_GND on TOP: 28.75,16.1 28.75,22.61 28.52,22.83 27.56,22.83 27.35,23.04 27.35,24.64 27.73,25.02 31.29,25.02 32.18,24.13 32.18,6.55 31.34,5.71 19.58,5.71 19.1,6.2 19.1,11.05 19.63,11.58 21.84,11.58 22.42,11 22.42,8.15 23.14,7.44 29.79,7.44 30.78,8.43 30.78,14.07
VDD_IN_GND on BOTTOM: 21.89,11.43 20.24,11.43 19.73,10.92 19.73,6.73 20.75,5.71 31.29,5.71 32.3,6.73 32.3,16.13 31.92,16.51 29.89,16.51 29.64,16.26 29.64,15.24 30.78,14.1 30.78,8.51 29.76,7.49 23.03,7.49 22.4,8.13 22.4,10.92
VDD_LVD_5V on TOP: 12.11,47.62 12.11,43.18 12.24,43.05 17.7,43.05 18.59,43.94 18.59,53.98 18.46,54.1 17.45,54.1 17.19,53.85 17.19,52.83 15.54,51.18 13.38,51.18 12.87,50.67 12.87,49.53 12.49,49.15 8.56,49.15 8.3,48.9 8.3,48.26 8.68,47.88 11.86,47.88
VDD_LVD_5V on BOTTOM: 13.89,52.96 18.46,52.96 18.97,53.47 18.97,55.12 18.72,55.37 17.95,55.37 17.7,55.12 17.7,54.23 17.19,53.72 13.89,53.72 13.76,53.59 13.76,53.09
VDD_LVD_5V on BOTTOM: 13.64,82.55 16.56,82.55 17.06,83.06 17.06,84.2 17.32,84.45 18.21,84.45 18.33,84.33 18.33,81.28 18.21,81.15 16.3,81.15 15.67,81.79 13.76,81.79 13.64,81.92
VDD_LVD_5V on ART03: 17.5,52.96 17.17,53.29 17.17,54.81 17.18,54.83 17.18,62.94 14.75,65.37 14.75,81.94 17.17,84.35 18.18,84.35 18.33,84.2 18.33,76.52 18.34,76.51 18.34,67.68 20.85,65.18 20.85,54.61 19.68,53.44 18.82,53.44 18.33,52.96
VDD_MMC1_SD on TOP: 79.8,104.9 81.2,104.9 81.58,105.28 81.58,105.79 81.2,106.17 80.18,106.17 79.8,105.79
VDD_MMC1_SD on TOP: 79.68,112.01 79.68,108.46 80.06,108.08 81.45,108.08 81.58,108.2 81.58,108.97 81.45,109.09 80.95,109.09 80.44,109.6 80.44,112.01 80.31,112.14 79.8,112.14
VDD_MMC1_SD on BOTTOM: 79.75,110.11 79.75,105.61 80.01,105.36 80.84,105.36 81.76,106.27 81.76,106.55 82.01,106.81 82.22,106.81 82.44,107.04 82.44,108.71 82.06,109.09 81.1,109.09 80.59,109.6 80.59,109.98 80.44,110.13 79.78,110.13
VDD_PHY1_1V1 on TOP: 85.17,40.26 85.17,39.12 85.3,38.99 89.96,38.99 90.09,39.12 90.09,40.13 89.71,40.51 85.43,40.51
VDD_PHY1_1V1 on TOP: 95.8,28.32 95.8,27.05 95.93,26.92 96.95,26.92 97.07,27.05 97.07,28.19 96.82,28.45 95.93,28.45
VDD_PHY1_1V1 on BOTTOM: 85.06,40.28 85.06,39.52 85.24,39.34 86.51,39.34 86.91,39.75 86.91,40.01 86.56,40.36 85.14,40.36
VDD_PHY1_1V1 on BOTTOM: 95.88,27.84 95.88,27 96.06,26.82 97.28,26.82 97.51,27.05 97.51,27.89 96.82,28.57 95.83,28.57 95.55,28.3 95.55,28.17
VDD_PHY1_1V1 on ART03: 85.11,40.28 85.11,39.62 85.26,39.47 86.79,39.47 86.89,39.57 86.89,40.28 86.79,40.39 85.21,40.39
VDD_PHY1_3V3 on TOP: 82.6,35.56 82.6,33.78 82.72,33.66 84.12,33.66 84.25,33.78 84.25,35.05 83.61,35.69 82.72,35.69
VDD_PHY1_3V3 on BOTTOM: 83.21,34.8 83.84,34.8 84.27,34.37 84.27,34.01 83.89,33.63 83.28,33.63 83.13,33.78 83.13,34.72
VDD_PHY2_1V1 on TOP: 119.72,26.54 119.85,26.67 119.85,28.07 119.72,28.19 118.83,28.19 118.7,28.07 118.7,26.67 118.83,26.54
VDD_PHY2_1V1 on TOP: 108.47,39.65 108.47,39.12 108.58,39.01 113.35,39.01 113.46,39.12 113.46,40.26 113.2,40.51 108.4,40.51 108.23,40.34 108.23,39.89
VDD_PHY2_1V1 on BOTTOM: 118.74,27.41 118.74,26.57 118.87,26.44 119.86,26.44 120.11,26.7 120.11,27.43 119.66,27.89 119.58,27.89 119.2,27.51 118.84,27.51
VDD_PHY2_1V1 on ART03: 108.3,40.34 110.36,40.34 110.54,40.16 110.54,39.88 110.36,39.7 108.35,39.7 108.23,39.83 108.23,40.26
VDD_PHY2_3V3 on TOP: 102.88,38.61 104.53,38.61 104.66,38.48 104.66,37.59 104.4,37.34 102.88,37.34 102.63,37.59 102.63,38.35
VDD_RTC on TOP: 121.05,61.34 121.05,60.35 121.33,60.07 124.61,60.07 124.76,60.22 124.76,61.32 124.61,61.47 121.18,61.47
VDD_RTC on TOP: 119.52,64.9 117.95,64.9 117.65,64.59 115.85,64.59 115.74,64.69 115.74,66.7 115.82,66.78 116.91,66.78 117.65,66.04 119.55,66.04 119.67,65.93 119.67,65.05
VDD_RTC on ART03: 115.72,65 115.72,63.4 118.87,60.25 123.47,60.25 124.23,61.01 124.23,61.52 124.1,61.65 119.38,61.65 117.24,63.78 117.24,64.95 117.12,65.07 115.79,65.07
VDD_SOM_5V on TOP: 69.52,95 70.02,94.49 70.02,90.81 69.77,90.55 66.11,90.55 65.91,90.75 65.91,94.67 66.24,95 ; 3 cut-outs
VDD_SOM_5V_R on TOP: 66.98,98.17 66.98,96.52 67.33,96.16 69.82,96.16 70.02,96.37 70.02,98.12 69.85,98.3 67.1,98.3
VDD_SOM_5V_R on TOP: 38.96,85.39 38.96,86.46 39.26,86.77 47.93,86.77 48.03,86.87 48.05,86.87 48.05,88.29 47.82,88.52 37.97,88.52 37.74,88.29 37.74,85.33 38.05,85.03 38.59,85.03
VDD_SOM_5V_R on POW04: 44.73,86.94 55.04,86.94 57.2,89.1 57.2,92.61 59.86,95.28 69.29,95.28 70.18,96.16 70.18,100.97 70.15,100.97 69.64,101.47 45.39,101.47 44.19,100.28 44.19,87.48
VDD_SOM_5V_SW on TOP: 37.69,82.27 37.77,82.19 38.27,82.19 38.38,82.3 38.38,83.82 37.45,84.75 36.23,84.75 35.76,85.22 35.76,88.24 35.51,88.49 34.95,88.49 34.74,88.29 34.74,84.73 35.61,83.87 36.8,83.87 36.98,83.69 36.98,83.01 37.05,82.93 37.61,82.93 37.69,82.85
VDD_SOM_5V_SW on TOP: 37.85,79.26 36.46,79.26 36.22,79.5 36.22,79.73 36.32,79.83 37.44,79.83 37.69,80.09 37.69,80.21 37.74,80.26 37.92,80.26 37.97,80.21 37.97,79.38
VDD_SOM_5V_SW on BOTTOM: 36.39,84.18 37.94,84.18 38.07,84.05 38.07,83.06 37.74,82.73 37.74,79.4 37.54,79.2 36.37,79.2 36.19,79.38 36.19,83.97
VDD_USB0_VBUS on TOP: 62.66,10.92 63.04,10.54 65.07,10.54 65.32,10.29 65.32,9.02 64.94,8.64 59.74,8.64 59.48,8.89 59.48,10.67 59.74,10.92
VDD_USB0_VBUS on TOP: 60.37,24.77 62.53,24.77 62.91,25.15 62.91,26.04 63.04,26.16 63.8,26.16 63.93,26.04 63.93,21.72 63.8,21.59 62.66,21.59 62.53,21.72 62.53,23.62 62.15,24 60.37,24 60.24,24.13 60.24,24.64
VDD_USB0_VBUS on ART03: 53.51,8.51 53.51,4.19 53.89,3.81 57.32,3.81 58.21,4.7 58.21,7.49 59.36,8.64 61.01,8.64 61.26,8.89 61.26,19.56 62.15,20.45 63.8,20.45 64.31,20.95 64.31,23.24 63.67,23.88 61.26,23.88 60.24,22.86 60.24,20.07 59.23,19.05 59.23,10.54 56.94,8.26 54.91,8.26 54.4,8.76 53.77,8.76
VDD_USB_1V8 on TOP: 122.6,32 123.49,32 123.74,32.26 123.74,33.02 123.62,33.15 122.47,33.15 122.35,33.02 122.35,32.26
VDD_USB_1V8 on ART03: 122.35,33.15 122.35,31.7 122.98,31.06 133.24,31.06 134.57,29.74 134.57,26.8 134.95,26.42 136.32,26.42 136.7,26.8 136.7,31.78 134.82,33.66 122.86,33.66
VDDA_PHY1_1V1 on TOP: 94.53,28.32 95.4,28.32 95.53,28.19 95.53,27.05 95.32,26.85 94.64,26.85 94.41,27.08 94.41,28.19
VDDA_PHY1_1V1 on BOTTOM: 85.64,31.11 87.04,31.11 87.17,30.99 87.17,30.35 86.66,29.84 86.66,28.32 86.91,28.07 88.18,28.07 88.57,28.45 88.57,29.34 88.69,29.46 91.11,29.46 91.23,29.34 91.23,28.24 91.66,27.81 95.32,27.81 95.53,27.61 95.53,27 95.32,26.8 86.15,26.8 85.64,27.3
VDDA_PHY2_1V1 on TOP: 118.32,27.18 118.19,27.05 116.81,27.05 116.56,27.3 116.56,28.63 116.68,28.75 117.98,28.75 118.32,28.41
VDDA_PHY2_1V1 on BOTTOM: 108.89,31.11 110.28,31.11 110.41,30.99 110.41,30.35 109.9,29.84 109.9,28.32 110.16,28.07 111.43,28.07 111.81,28.45 111.81,29.34 111.93,29.46 114.35,29.46 114.47,29.34 114.47,28.78 114.8,28.45 116.1,28.45 116.81,29.16 117.62,29.16 117.78,29.01 117.78,26.92 117.65,26.8 109.39,26.8 108.89,27.3
VDDA_PHY2_3V3 on TOP: 101.1,38.48 102.12,38.48 102.24,38.35 102.24,37.21 102.12,37.08 101.1,37.08 100.97,37.21 100.97,38.35
(no net) on TOP: 54.02,41.52 54.49,41.52 54.89,41.91 54.89,42.32 55.09,42.52 62.76,42.52 62.91,42.67 62.91,45.11 62.66,45.36 54.58,45.36 53.76,44.54 53.76,41.78
(no net) on TOP: 74.85,95.89 74.27,96.47 70.68,96.47 70.53,96.32 70.53,94.89 70.68,94.74 76.68,94.74 78.13,96.19 79.14,96.19 79.29,96.04 79.29,94.23 79.65,93.88 84.58,93.88 86.79,96.09 86.79,98.09 87.12,98.42 88.34,98.42 88.41,98.5 88.41,98.93 88.34,99.01 82.57,99.01 81.86,98.3 80.51,98.3 80.13,97.92 80.13,97.49 80.44,97.18 80.84,97.18 80.95,97.08 80.95,96.29 81.02,96.22 82.14,96.22 82.44,95.91 82.44,94.54 82.14,94.23 79.98,94.23 79.8,94.41 79.8,96.37 79.63,96.55 77.97,96.55 77.31,95.89
(no net) on TOP: outline of 140 points within 7.79,23.11 62.78,53.72
(no net) on TOP: 78.81,99.07 79.82,99.07 80.11,99.36 88.31,99.36 88.41,99.47 88.41,101.83 88.07,102.17 78.8,102.17 78.52,101.89 78.52,99.36
(no net) on TOP: 75.26,96.49 75.26,96.24 75.31,96.19 77.06,96.19 77.54,96.67 77.54,100.74 77.21,101.07 76.83,101.07 76.53,100.76 76.53,96.75 76.3,96.52 75.28,96.52
(no net) on TOP: 50.49,38.96 50.49,38.71 50.54,38.66 52.29,38.66 52.78,39.14 52.78,43.26 52.47,43.56 52.04,43.56 51.76,43.28 51.76,39.22 51.53,38.99 50.52,38.99
(no net) on BOTTOM: 86.66,108.97 86.66,106.55 86.79,106.43 87.68,106.43 87.8,106.55 87.8,108.97 87.68,109.09 86.79,109.09
(no net) on GND02: outline of 103 points within 5.51,0.51 174.49,124.49
AUDIO_GND on TOP: 48.36,16.38 50.36,16.38 50.85,15.9 50.85,15.24 50.77,15.16 48.03,15.16 47.85,15.34 47.85,15.88
AUDIO_GND on TOP: 38.15,29.08 38.15,27.81 38.27,27.69 40.18,27.69 40.18,29.08 40.03,29.24 38.3,29.24
AUDIO_GND on BOTTOM: 38.22,29.18 38.22,27.74 40.13,27.74 40.13,29.18
AUDIO_GND on BOTTOM: 47.88,15.14 50.75,15.14 50.87,15.27 50.87,15.9 50.36,16.41 48.33,16.41 47.82,15.9 47.82,15.19
CVCC_1V2 on TOP: 150.8,21.97 151.68,21.97 151.81,22.1 151.81,22.99 151.56,23.24 150.92,23.24 150.67,22.99 150.67,22.1
CVCC_1V2 on BOTTOM: 151.68,36.07 151.68,35.31 151.56,35.18 147.62,35.18 147.24,34.8 147.24,33.66 146.22,32.64 144.95,32.64 144.7,32.38 144.7,27.43 146.1,26.04 150.16,26.04 150.29,25.91 150.29,25.02 150.15,24.88 150.16,24.87 150.16,24.64 150.24,24.56 151.2,24.56 151.43,24.79 151.43,25.78 151.68,26.04 152.95,26.04 153.08,25.91 153.08,24.89 151.81,23.62 151.81,22.73 151.56,22.48 150.8,22.48 150.54,22.73 150.54,23.24 150.41,23.37 146.35,23.37 143.18,26.54 143.18,32.64 143.94,33.4 145.84,33.4 146.22,33.78 146.22,35.18 147.24,36.2 151.56,36.2
DEBUG_VBUS_5V on TOP: 74.57,16.33 74.34,16.56 74.34,17.81 74.04,18.11 72.92,18.11 72.69,18.34 72.69,18.54 73.33,18.54 73.33,18.82 72.69,18.82 72.69,19.05 75.66,19.05 75.76,18.95 75.76,16.48 75.61,16.33
DEBUG_VBUS_5V on TOP: 75.1,11.05 77.52,11.05 78.02,10.54 80.06,10.54 80.06,9.53 79.93,9.4 77.39,9.4 77.14,9.14 76.12,9.14 75.48,8.51 74.47,8.51 74.34,8.64 74.34,10.29
DEBUG_VBUS_5V on ART03: 73.33,19.18 73.33,14.86 73.83,14.35 73.83,13.08 73.45,12.7 72.44,12.7 72.44,8.89 72.18,8.64 68.63,8.64 68.37,8.38 68.37,5.33 69.64,4.06 72.69,4.06 73.07,4.45 73.07,7.11 74.47,8.51 75.87,8.51 76.12,8.76 76.12,18.92 75.74,19.3 73.45,19.3
IOVCC_3V3 on TOP: 149.27,23.11 149.27,22.23 149.53,21.97 150.16,21.97 150.41,22.23 150.41,22.99 150.16,23.24 149.4,23.24
IOVCC_3V3 on ART03: 148.79,18.67 149.07,18.95 149.07,22.05 149.7,22.68 150.36,22.68 150.92,23.24 151.15,23.24 151.16,23.23 157.18,23.23 159.25,25.3 159.25,36.45 158.47,37.24 152.32,37.24 151.99,36.91 151.99,35.92 152.19,35.71 155.09,35.71 155.85,34.95 155.85,25.81 155.15,25.11 151.6,25.11 151.08,24.59 149.78,24.59 149.53,24.84 149.53,25.27 149.42,25.37 149.22,25.37 149.07,25.22 149.07,24.89 148.51,24.33 147.9,24.33 147.34,23.77 147.37,23.75 147.37,19.05 147.75,18.67
ISO_485 on TOP: 109.65,103.38 112.82,103.38 113.08,103.63 113.71,103.63 113.84,103.5 113.84,101.98 113.58,101.73 109.65,101.73 109.39,101.98 109.39,103.12
ISO_485 on TOP: 122.47,106.93 122.47,104.39 122.73,104.14 124.63,104.14 125.01,104.52 125.01,107.06 124.89,107.19 122.73,107.19
ISO_485 on TOP: 116.12,107.44 116.12,104.27 116.25,104.14 116.63,104.14 116.76,104.27 116.76,106.17 117.39,106.81 117.9,106.81 118.16,107.06 118.16,107.95 118.03,108.08 116.76,108.08
ISO_485 on TOP: 128.82,107.44 128.82,104.39 129.08,104.14 129.46,104.14 129.59,104.27 129.59,106.81 130.22,107.44 130.22,108.08 129.46,108.08
ISO_485 on TOP: 127.05,109.22 129.08,109.22 129.08,110.24 128.82,110.49 127.05,110.49 126.79,110.24 126.79,109.47
ISO_485 on TOP: 134.92,106.93 134.92,104.39 135.17,104.14 137.08,104.14 137.46,104.52 137.46,106.93 137.21,107.19 135.17,107.19
ISO_485 on TOP: 114.35,109.22 116.38,109.22 116.38,110.24 116.12,110.49 114.35,110.49 114.09,110.24 114.09,109.47
ISO_485 on BOTTOM: 125.52,107.37 122.98,107.37 122.09,108.25 122.09,109.42 122.86,110.19 125.45,110.19 125.9,109.73 125.9,107.75
ISO_485 on BOTTOM: 130.2,108.1 129.79,107.7 127.05,107.7 126.67,108.08 126.67,110.24 126.92,110.49 129.71,110.49 130.2,110.01
ISO_485 on BOTTOM: 113.58,101.73 113.84,101.98 113.84,103.5 113.58,103.76 103.81,103.76 103.42,103.38 103.42,102.11 103.81,101.73
ISO_485 on BOTTOM: 116.89,110.19 119.43,110.19 120.32,109.3 120.32,108.13 119.55,107.37 116.96,107.37 116.51,107.82 116.51,109.8
ISO_485 on BOTTOM: 135.94,107.37 133.4,107.37 132.51,108.25 132.51,109.42 133.27,110.19 135.86,110.19 136.32,109.73 136.32,107.75
ISO_485 on GND02, POW04, GND05: 103.93,101.73 103.42,102.23 103.42,104.78 105.84,107.19 105.84,124.49 137.46,124.49 137.46,103.76 136.95,103.25 115.24,103.25 113.71,101.73
ISO_CAN on TOP: 159.81,107.19 159.81,104.14 160.07,103.89 161.34,103.89 161.59,104.14 161.59,107.31 161.46,107.44 160.07,107.44
ISO_CAN on TOP: 148.38,107.06 148.38,104.01 148.64,103.76 149.91,103.76 150.16,104.01 150.16,107.19 150.03,107.31 148.64,107.31
ISO_CAN on TOP: 167.43,102.74 167.43,101.47 167.69,101.22 171.88,101.22 172,101.35 172,102.87 171.88,103 167.69,103
ISO_CAN on BOTTOM: 140.76,104.39 142.03,104.39 142.29,104.65 142.79,104.65 142.92,104.52 142.92,103.25 142.67,103 140.89,103 140.64,103.25 140.64,104.27
ISO_CAN on BOTTOM: 159.56,106.93 159.18,106.55 156.51,106.55 156.38,106.68 156.38,110.11 156.64,110.36 159.43,110.36 159.56,110.24
ISO_CAN on BOTTOM: 171.5,101.09 171.88,101.47 171.88,102.74 171.62,103 162.1,103 161.72,102.62 161.72,101.47 162.1,101.09
ISO_CAN on BOTTOM: 152.19,104.52 153.46,104.52 153.72,104.78 154.22,104.78 154.35,104.65 154.35,103.38 154.1,103.12 152.32,103.12 152.07,103.38 152.07,104.39
ISO_CAN on BOTTOM: 145.33,110.24 147.75,110.24 148.13,109.86 148.13,107.31 147.75,106.93 145.46,106.93 144.95,107.44 144.95,109.86
ISO_CAN on BOTTOM: 152.32,110.74 154.73,110.74 155.11,110.36 155.11,107.82 154.73,107.44 152.45,107.44 151.94,107.95 151.94,110.36
ISO_CAN on BOTTOM: 139.49,109.86 139.49,107.95 140,107.44 143.18,107.44 143.68,107.95 143.68,109.73 143.18,110.24 139.87,110.24
ISO_CAN on GND02, POW04, GND05: 161.97,101.09 159.94,103.12 154.1,103.12 153.97,103 139.37,103 138.73,103.63 138.73,124.49 166.04,124.49 166.04,109.98 169.46,106.55 171.12,106.55 172,105.66 172,101.35 171.75,101.09
Net_802 on TOP (solid shape): outline of 104 points within 147.16,83.62 151.01,87.32
Net_804 on TOP (solid shape): 145.27,86.28 145.27,86.25 145.05,86.25 144.65,86.15 144.29,85.96 144.03,85.74 143.82,85.47 143.74,85.27 143.69,85.07 143.69,83.63 142.74,83.63 142.73,85.01 142.67,85.34 142.52,85.65 142.29,85.87 142.01,86.04 141.71,86.17 141.39,86.25 141.16,86.25 141.16,86.29 141.16,87.25 141.91,87.16 142.58,86.83 142.93,86.52 143.21,86.15 143.7,86.68 144.3,87.08 144.77,87.22 145.26,87.28
Net_805 on TOP (solid shape): 138.05,87.26 138.12,86.61 138.34,86.01 138.55,85.7 138.88,85.51 139.25,85.58 139.52,85.84 139.82,86.52 139.91,87.26 140.86,87.26 141.18,83.65 140.2,83.64 140.1,85.17 139.85,84.91 139.56,84.7 139.4,84.61 138.99,84.54 138.57,84.62 138.2,84.84 137.89,85.14 137.75,83.65 136.77,83.65 136.78,83.7 136.79,83.68 137.22,87.19 137.22,87.23
VIO on TOP: 71.88,15.57 71.73,15.72 71.73,18.08 71.8,18.16 71.98,18.16 71.98,17.45 72.23,17.45 72.23,18.16 72.39,18.16 72.54,18.01 72.54,17.42 72.69,17.27 73.83,17.27 74.01,17.09 74.01,15.7 73.88,15.57
WIFI_2V2 on TOP: 43.61,96.01 50.08,96.01 50.34,96.27 50.34,97.28 50.72,97.66 50.72,100.2 50.59,100.33 49.96,100.33 49.7,100.08 49.32,100.08 48.81,99.57 48.81,98.3 48.05,97.54 48.03,97.54 47.75,97.26 43.56,97.26 43.38,97.08 43.38,96.24
N20390757 on TOP: 19.22,88.52 19.22,86.23 19.48,85.98 22.53,85.98 22.78,86.23 22.78,86.74 22.53,87 20.37,87 20.24,87.12 20.24,88.39 19.99,88.65 19.35,88.65
N21392930 on TOP: 88.33,36.72 89.11,35.94 89.11,35.05 89.37,35.05 89.37,36.32 90.22,37.17 90.22,37.99 89.98,38.23 87.42,38.23 87.17,37.97 87.17,36.83 87.3,36.7 88.31,36.7
N21405925 on TOP: 112.4,35.96 112.4,34.92 112.66,34.92 112.66,36.45 113.42,37.21 113.42,38.1 113.29,38.23 110.87,38.23 110.41,37.77 110.41,37.08 110.68,36.81 111.55,36.81
N21577422 on TOP: 38.65,67.31 38.65,66.04 38.91,65.79 40.05,65.79 41.7,67.44 41.7,71.32 41.22,71.81 40.36,71.81 39.9,71.35 39.9,68.55
N21838021 on TOP: 15.41,100.97 15.41,97.66 15.16,97.41 9.57,97.41 9.06,97.92 9.06,100.71 9.57,101.22 15.16,101.22
N21884472 on TOP: 25.83,17.53 25.07,16.76 25.07,13.72 24.68,13.34 23.03,13.34 22.53,13.84 22.53,24.38 23.19,25.04 25.4,25.04 25.83,24.61
N21885584 on TOP: 36.19,82.37 36.88,81.69 37.54,81.69 37.64,81.79 37.64,81.86 37.51,81.99 37.18,81.99 36.72,82.45 36.72,82.78 36.61,82.89 36.61,83.43 36.57,83.46 36.09,83.46 36.06,83.44 36.06,82.85 36.19,82.73
N22325526 on TOP: 121.31,21.87 122.09,21.87 122.91,21.06 125.62,21.06 125.8,20.88 125.8,19.58 125.62,19.41 124.13,19.41 123.74,19.79 122.5,19.79 121.2,21.08 121.2,21.77
N22325526 on BOTTOM: 128.52,17.68 129.71,16.48 129.71,11.28 129.92,11.07 135.63,11.07 136.14,11.58 136.14,18.92 135.84,19.23 130.15,19.23 129.16,20.22 124.23,20.22 124.08,20.07 124.08,19.46 124.15,19.38 124.15,17.93 124.41,17.68
N22325538 on TOP: 128.55,19.76 131.95,19.76 132.15,19.56 132.15,17.93 131.9,17.68 129.38,17.68 128.95,18.11 126.89,18.11 126.62,18.39 126.62,19.53 126.63,19.55 126.63,20.64 126.82,20.83 127.48,20.83
N22325538 on ART03: 130.25,18.26 136.09,18.26 136.42,17.93 136.42,11.61 135.86,11.05 129.94,11.05 129.41,11.58 129.41,13.13 129.64,13.36 130.6,13.36 131.16,13.92 131.16,16.03 130.12,17.07 130.12,18.14
N22387188 on TOP: 32.53,35.99 33.22,35.99 33.27,36.04 33.27,36.2 32.97,36.5 32.79,36.5 32.2,37.08 32.2,37.74 32.15,37.8 31.7,37.8 31.64,37.74 31.64,36.88
N22684386 on TOP: 43.23,101.09 43.23,98.93 43.66,98.5 46.86,98.5 47.8,99.44 47.8,100.2 48.05,100.46 49.2,100.46 49.32,100.58 49.32,101.22 49.07,101.47 43.61,101.47

Small or netless copper shapes (teardrops, artwork), in the pictures only: 8 on TOP, 1 on BOTTOM

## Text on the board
